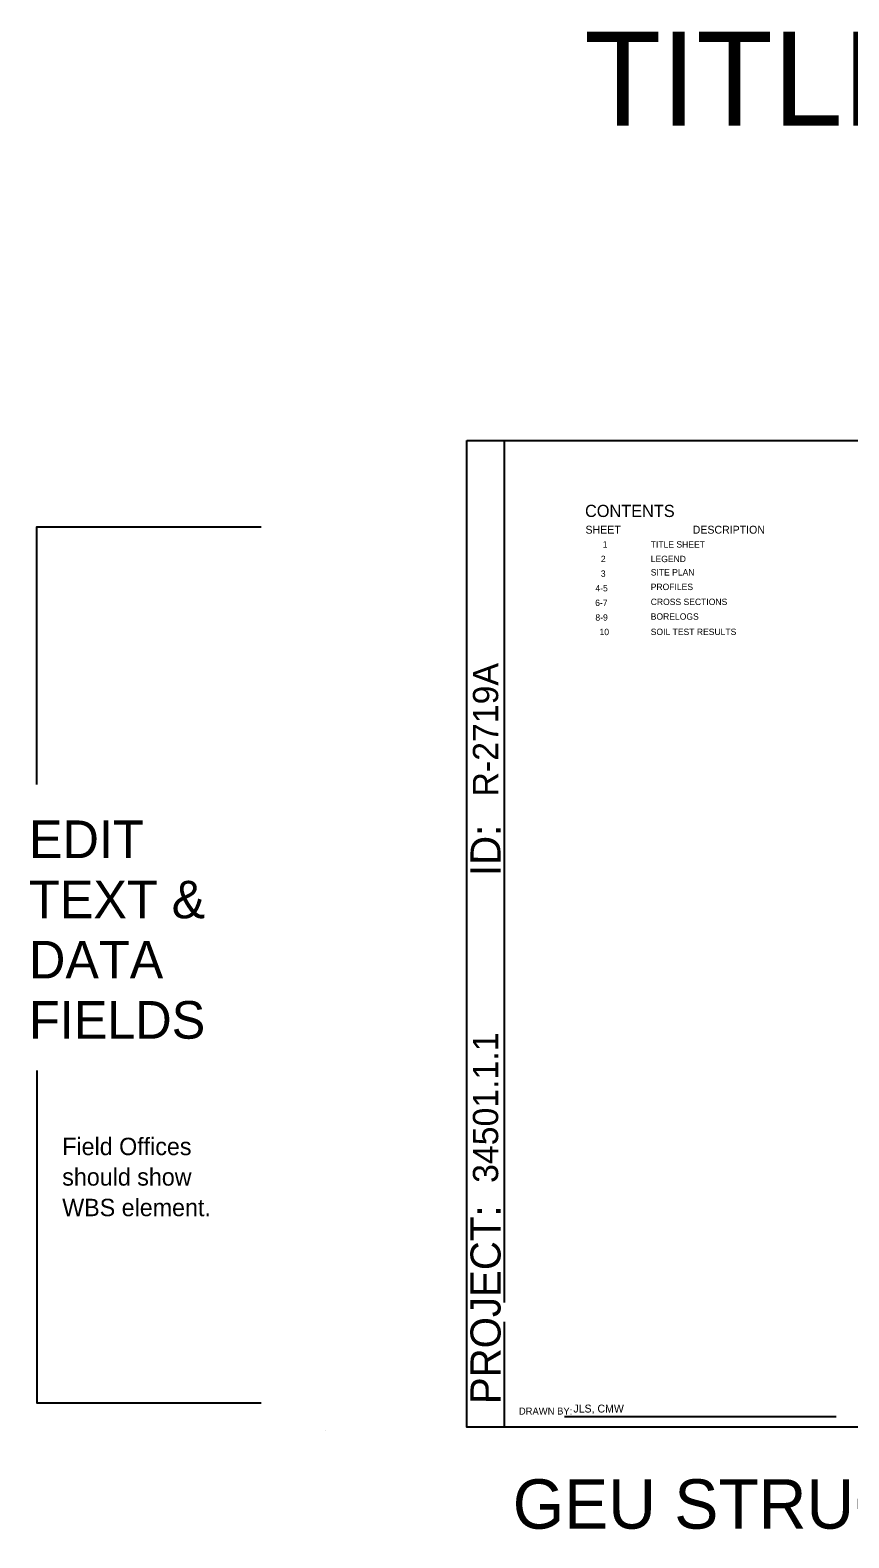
# Model space of a CAD drawing. Extents: x 278710 to 279187, y 171464 to 171625.
# Drawn here: x 278709.7 to 278796.7, y 171464.3 to 171624.6 of the extents above; entities that cross this region are included whole.
import ezdxf

# ---------------------------------------------------------------- set-up
doc = ezdxf.new("R2010")
doc.units = 0
doc.layers.add('Geotech Sheets and Borders Cell', color=7, linetype='Continuous')
doc.layers.add('Prop Strc Sect_ Misc - User Comment (Tx - small)', color=7, linetype='Continuous')

msp = doc.modelspace()

# ---------------------------------------------------------------- linework, layer by layer
at = {"layer": 'Geotech Sheets and Borders Cell'}
for p, q in [((278760.06, 171580.95), (278760.06, 171489.33)), ((278760.06, 171487.27), (278760.06, 171476.08)), ((278766.45, 171477.22), (278795.32, 171477.22)), ((278741.09, 171475.75), (278741.09, 171475.75))]:
    msp.add_line(p, q, dxfattribs=at)
msp.add_lwpolyline([(278756.09, 171580.95), (278907.34, 171580.95), (278907.34, 171476.08), (278756.09, 171476.08)], close=True, dxfattribs=at)
for points in [[(278710.39, 171544.39), (278710.39, 171571.77), (278734.25, 171571.77)], [(278710.39, 171513.98), (278710.39, 171478.65), (278734.25, 171478.65)]]:
    msp.add_lwpolyline(points, dxfattribs=at)

# ---------------------------------------------------------------- texts
for s, height, rotation, p in [('CONTENTS', 1.295, 359.9916, (278768.65, 171572.83)), ('R-2719A', 2.688, 90, (278759.42, 171543.12)), ('ID:', 3.195, 89.9873, (278759.67, 171534.66)), ('34501.1.1', 2.688, 90, (278759.42, 171502.04)), ('PROJECT:', 3.195, 89.9873, (278759.67, 171478.52)), ('DRAWN BY:', 0.749, 0.1322, (278761.62, 171477.4))]:
    msp.add_text(s, height=height, rotation=rotation, dxfattribs=at).set_placement(p)
for s, height, p in [('SHEET', 0.84, (278768.7, 171571.06)), ('DESCRIPTION', 0.84, (278780.09, 171571.06)), ('1', 0.68, (278770.53, 171569.58)), ('TITLE SHEET', 0.68, (278775.63, 171569.58)), ('2', 0.68, (278770.33, 171568.03)), ('LEGEND', 0.68, (278775.63, 171568.03)), ('3', 0.68, (278770.33, 171566.47)), ('SITE PLAN', 0.68, (278775.63, 171566.61)), ('4-5', 0.68, (278769.75, 171564.92)), ('PROFILES', 0.68, (278775.63, 171565.06)), ('6-7', 0.68, (278769.73, 171563.37)), ('CROSS SECTIONS', 0.68, (278775.63, 171563.47)), ('8-9', 0.68, (278769.75, 171561.81)), ('BORELOGS', 0.68, (278775.63, 171561.91)), ('10', 0.68, (278770.19, 171560.27)), ('SOIL TEST RESULTS', 0.68, (278775.63, 171560.28)), ('EDIT', 4, (278709.57, 171536.57)), ('TEXT &', 4, (278709.57, 171530.17)), ('DATA', 4, (278709.57, 171523.77)), ('FIELDS', 4, (278709.57, 171517.37)), ('Field Offices', 1.848, (278713.1, 171504.99)), ('should show', 1.848, (278713.1, 171501.75)), ('WBS element.', 1.848, (278713.1, 171498.5)), ('JLS, CMW', 0.84, (278767.41, 171477.63)), ('GEU STRUCTURE TITLE SHEET, ENGLISH', 5.25, (278760.97, 171465.28))]:
    msp.add_text(s, height=height, dxfattribs=at).set_placement(p)
at = {"layer": 'Prop Strc Sect_ Misc - User Comment (Tx - small)'}
msp.add_text('TITLE SHEET: 11" x 17"', height=10, dxfattribs=at).set_placement((278768.57, 171614.44))

doc.saveas('drawing.dxf')
